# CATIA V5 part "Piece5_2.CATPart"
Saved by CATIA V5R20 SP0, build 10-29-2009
Part number: Pièce5
Bounding box of the stored display mesh (mm): x 0 to 5, y -7.796 to 60.482, z -89.779 to -55.203
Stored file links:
  C:\Users\ASUS\Desktop\Think Motion IAO\Piece5_2.CATPart
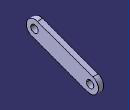
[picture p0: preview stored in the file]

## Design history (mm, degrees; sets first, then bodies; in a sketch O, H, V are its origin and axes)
Body1 (main body)
  Plane1: stored without definition
  Point1 "Point.G": stored without definition
  Point2 "Point.E": stored without definition
  Sketch1 on Plane1, origin (0, 0, 0), H (0, 1, 0), V (0, 0, 1)
    construction line L1 (0.0005, -63) -> (52.6852, -81.9821)
    line L2 (2.6463, -55.6567) -> (55.331, -74.6388)
    line L3 (50.0395, -89.3254) -> (-2.6453, -70.3433)
    arc A1 centre (52.6852, -81.9821) radius 7.8054 from (55.331, -74.6388) to (50.0395, -89.3254) cw
    arc A2 centre (0.0005, -63) radius 7.8054 from (-2.6453, -70.3433) to (2.6463, -55.6567) cw
    reference projected point E1 (0.0005, -63) from Point1
    reference projected point E2 (52.6852, -81.9821) from Point2
    circle A3 centre (52.6852, -81.9821) radius 3.5
    circle A4 centre (0.0005, -63) radius 3.5
    distance L1 L2 = 7.8054
    radius A3 = 3.5
    radius A4 = 3.5
    tangency: A1 L2, A2 L2, A1 L3, A2 L3
    concentricity: A2 E1, A1 E2
  Pad1: profile Sketch1, direction (1, 0, 0), length 5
